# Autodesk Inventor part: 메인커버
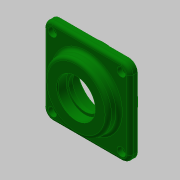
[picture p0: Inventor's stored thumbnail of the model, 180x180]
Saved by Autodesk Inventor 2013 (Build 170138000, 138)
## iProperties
Created: 2018-09
Part Number: 메인커버
Material: 알루미늄 6061
Document SubType Name: Modeling
Designer: mduedu
Density: 1 g/cm^3
Author: mduedu
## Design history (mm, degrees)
sketch "스케치1"
  geometry: L1 (-40, -40)-(40, -40); L2 (40, -40)-(40, 40); L3 (40, 40)-(-40, 40); L4 (-40, 40)-(-40, -40); L5 (-40, -40)-(40, 40); L6 (40, -40)-(-40, 40); 1 further point
  constraints: 12 end point, 2 midpoint, 2 parallel, 1 horizontal, 1 perpendicular
  dimensions: "d0" = 80 distance of L3.end L2.end; "d1" = 80 distance of L2.end L1.end
extrude "돌출1" new body sketch "스케치1" distance "d2" = 7; taper "d3" = 0 deg
sketch "스케치2"
  geometry: C1 r 30 at (0, 0); 1 further point
  constraints: 1 centre point, 1 coincident
  dimensions: "d4" = 60 diameter of C1
extrude "돌출2" join sketch "스케치2" distance "d5" = 10; taper "d6" = 0 deg
sketch "스케치3"
  geometry: C1 r 32.5 at (0, 0); 1 further point
  constraints: 1 centre point, 1 coincident
  dimensions: "d7" = 65 diameter of C1
extrude "돌출3" join sketch "스케치3" distance "d8" = 9; taper "d9" = 0 deg
sketch "스케치4"
  geometry: L1 (-32.5, -9)-(32.5, -9) reference; L2 (30, 17)-(-30, 17) reference; L3 (0, 17)-(0, -9); L4 (0, -9)-(23.5, -9); L5 (23.5, -9)-(23.5, 5); L6 (23.5, 5)-(0, 5); L7 (0, 5)-(0, -9); L8 (0, 5)-(15, 5); L9 (15, 5)-(15, 8.7); L10 (15, 8.7)-(0, 8.7); L11 (0, 8.7)-(0, 5); L12 (0, 8.7)-(17.5, 8.7); L13 (17.5, 8.7)-(17.5, 17); L14 (17.5, 17)-(0, 17); L15 (0, 17)-(0, 8.7); 1 further point
  constraints: 26 end point, 6 parallel, 3 horizontal, 3 perpendicular, 2 midpoint, 1 point on line
  dimensions: "d10" = 14 distance of L4.end L5.end; "d12" = 8.3 distance of L12.end L13.end; "d13" = 35 diameter of L13 L3; "d14" = 30 diameter of L9 L3; "d15" = 47 diameter of L5 L3
revolve "회전1" sketch "스케치4" stored, may be unused: angle "d16" = 90 deg
fillet "모깎기1" dims "d17" = 8
fillet "모깎기2" dims "d18" = 3
fillet "모깎기3" dims "d19" = 3
chamfer "모따기1" distance "d20" = 0.8; stored, may be unused: second distance "d21" = 2, angle "d22" = 30 deg
chamfer "모따기2" distance "d23" = 1; stored, may be unused: second distance "d24" = 2, angle "d25" = 30 deg
fillet "모깎기4" dims "d26" = 0.3
sketch "스케치5"
  geometry: A1 r 8 centre (-32, 32) between (-32, 40) and (-40, 32) reference; A2 r 8 centre (-32, -32) between (-40, -32) and (-32, -40) reference; A3 r 8 centre (32, -32) between (32, -40) and (40, -32) reference; A4 r 8 centre (32, 32) between (40, 32) and (32, 40) reference; 5 further points
  constraints: 4 coincident
hole "구멍1" sketch "스케치5" at (-32, 32), (32, 32), (32, -32), (-32, -32) diameter "d27" = 4.5; stored, may be unused: countersink angle "d31" = 90 deg, drill point angle "d33" = 118 deg; dims "d28" = 6, "d29" = 8, "d30" = 4.4, "d32" = 8
node "솔리드1"
